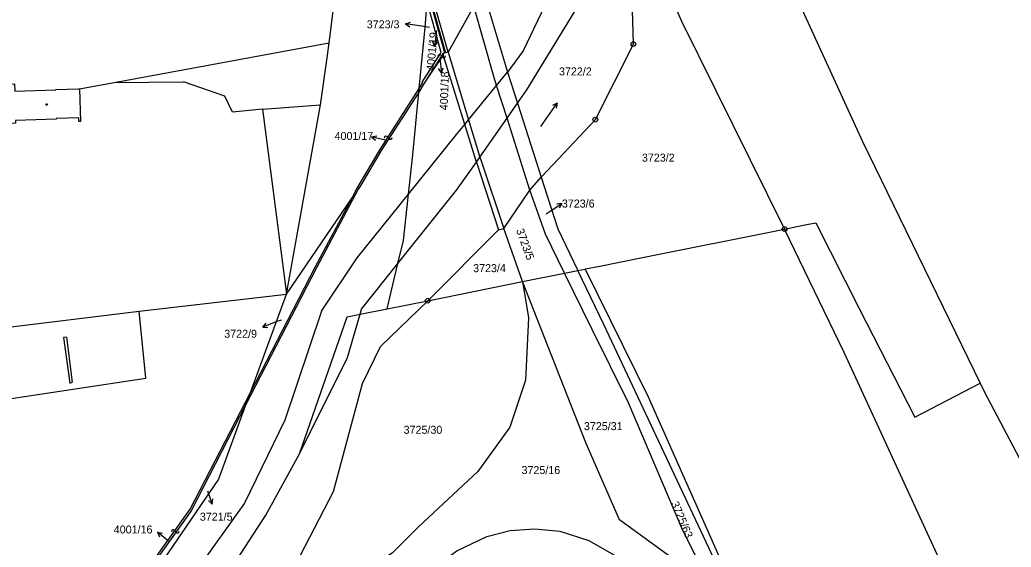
# Model space of a CAD drawing. Extents: x -747779 to -747197, y -965543 to -964919.
# Drawn here: x -747601.4 to -747390.8, y -965349.9 to -965237.8 of the extents above; entities that cross this region are included whole.
import ezdxf

# ---------------------------------------------------------------- set-up
doc = ezdxf.new("R2010")
doc.units = 0
for name, color, linetype in [('Hranice parcel', 7, 'Continuous'), ('Parcelní čísla', 7, 'Continuous'), ('Pop  PČ popisy', 7, 'Continuous'), ('Vnitřní kresba', 7, 'Continuous'), ('Značky bodu BP', 7, 'Continuous'), ('Značky budov', 7, 'Continuous'), ('Značky kultur', 7, 'Continuous')]:
    doc.layers.add(name, color=color, linetype=linetype)

msp = doc.modelspace()

# ---------------------------------------------------------------- linework, layer by layer
at = {"layer": 'Hranice parcel'}
for p, q in [((-747514.75, -965231.66), (-747511.04, -965244.8)), ((-747511.04, -965244.8), (-747511.35, -965244.91)), ((-747515.51, -965251.29), (-747516.68, -965253.18)), ((-747516.68, -965253.18), (-747516.6, -965252.37)), ((-747493.09, -965273.99), (-747490.69, -965271.24)), ((-747498.6, -965282.12), (-747493.09, -965273.99)), ((-747544.78, -965296.1), (-747530.86, -965275.61)), ((-747494.62, -965293.42), (-747498.6, -965282.12)), ((-747494.62, -965293.42), (-747485.73, -965291.64)), ((-747485.73, -965291.64), (-747482.89, -965291.07)), ((-747482.89, -965291.07), (-747481.32, -965290.75)), ((-747514.8, -965297.48), (-747494.62, -965293.42)), ((-747552.46, -965316.97), (-747544.78, -965296.1)), ((-747523.38, -965299.2), (-747514.8, -965297.48)), ((-747553.47, -965319.72), (-747552.46, -965316.97))]:
    msp.add_line(p, q, dxfattribs=at)
for points in [[(-747535.74, -965242.71), (-747531.85, -965211.79), (-747531.66, -965185.87), (-747538.81, -965117.67), (-747546.28, -965074.93), (-747546.46, -965062.18)], [(-747468.41, -965145.2), (-747466.29, -965153.89), (-747464.12, -965160.1), (-747445.94, -965212.26), (-747440.57, -965223.99), (-747422.43, -965263.63), (-747397.43, -965314.99)], [(-747490.69, -965271.24), (-747489.44, -965269.91), (-747487.1, -965267.42), (-747479.18, -965259.01), (-747471.1, -965242.94), (-747471.94, -965213.78), (-747472.02, -965212.77)], [(-747472.02, -965212.77), (-747460.89, -965238.09), (-747438.98, -965282.25)], [(-747514.78, -965232.07), (-747511.25, -965244.76), (-747511.35, -965244.91)], [(-747516.6, -965252.37), (-747515.34, -965239.4), (-747514.92, -965233.94)], [(-747516.6, -965252.37), (-747515.81, -965251.13), (-747515.95, -965251.03), (-747511.95, -965244.73), (-747514.92, -965233.94)], [(-747505, -965234.87), (-747510.48, -965244.69), (-747511.04, -965244.8)], [(-747588.73, -965252.47), (-747581.39, -965251.12), (-747535.74, -965242.71)], [(-747544.78, -965296.1), (-747537.6, -965255.87), (-747536.14, -965245.88), (-747535.74, -965242.71)], [(-747511.35, -965244.91), (-747511.54, -965245.21), (-747515.51, -965251.29)], [(-747511.35, -965244.91), (-747511.61, -965245), (-747515.51, -965251.29)], [(-747633.05, -965255.35), (-747633.06, -965254.31), (-747628.09, -965254.26), (-747628.08, -965255.3), (-747610.07, -965255.11), (-747610.11, -965251.53), (-747602.55, -965251.41), (-747602.51, -965252.93), (-747593.78, -965252.7), (-747593.79, -965252.6), (-747588.97, -965252.48), (-747588.73, -965252.47)], [(-747588.73, -965252.47), (-747588.55, -965259.42), (-747588.9, -965259.43), (-747588.92, -965258.62), (-747593.7, -965258.74), (-747593.7, -965258.94), (-747602.35, -965259.16), (-747602.34, -965259.76), (-747610.02, -965259.88), (-747610.02, -965260.13), (-747632.99, -965260.36), (-747638.07, -965260.41), (-747638.11, -965256.51), (-747633.04, -965256.38), (-747633.05, -965255.35)], [(-747516.68, -965253.18), (-747524.65, -965265.56), (-747529.03, -965272.91), (-747529.53, -965273.75), (-747538.42, -965290.51), (-747553.47, -965319.72)], [(-747530.86, -965275.61), (-747529.79, -965273.6), (-747524.88, -965265.35), (-747516.6, -965252.37)], [(-747523.38, -965299.2), (-747521.12, -965289.61), (-747519.96, -965284.68), (-747518.88, -965274.83), (-747517.97, -965266.5), (-747516.68, -965253.18)], [(-747490.69, -965271.24), (-747487.17, -965282.18), (-747482.89, -965291.07)], [(-747485.73, -965291.64), (-747489.75, -965283.38), (-747493.09, -965273.99)], [(-747552.46, -965316.97), (-747538.72, -965290.33), (-747530.86, -965275.61)], [(-747438.98, -965282.25), (-747435, -965281.45), (-747432.31, -965280.91), (-747423.15, -965299.11), (-747411.34, -965322.23), (-747397.43, -965314.99)], [(-747514.8, -965297.48), (-747499.75, -965282.4), (-747498.6, -965282.12)], [(-747481.32, -965290.75), (-747481.25, -965290.74), (-747478.23, -965290.13), (-747469.86, -965288.45), (-747438.98, -965282.25)], [(-747298.39, -965537.69), (-747318.1, -965501.72), (-747320.58, -965502.66), (-747342.67, -965465.16), (-747352.78, -965470.55), (-747357.13, -965461.03), (-747376, -965418.63), (-747377.18, -965415.98), (-747381.59, -965406.09), (-747382.39, -965404.29), (-747386.82, -965394.33), (-747387.63, -965392.51), (-747387.99, -965391.72), (-747426.3, -965308.51), (-747438.98, -965282.25)], [(-747445.23, -965379.92), (-747447.37, -965372.98), (-747460.79, -965345.82), (-747472.15, -965319.18), (-747479.89, -965303.62), (-747485.73, -965291.64)], [(-747481.32, -965290.75), (-747467.96, -965317.93), (-747448.87, -965361), (-747429.89, -965395.74), (-747424.56, -965401.33), (-747426.57, -965402.17)], [(-747494.62, -965293.42), (-747493.4, -965301.1), (-747494, -965314.35), (-747497.38, -965324.36), (-747504.12, -965333.82), (-747516.76, -965345.53), (-747522.34, -965351.17), (-747542.83, -965364.12), (-747548.91, -965365.21)], [(-747437.34, -965403.35), (-747436.67, -965405.18), (-747441.17, -965397.15), (-747449.31, -965379.9), (-747457.39, -965360.59), (-747463.67, -965351.63), (-747474.03, -965344.07), (-747481.12, -965327.83), (-747494.62, -965293.42)], [(-747647.24, -965306.07), (-747608.41, -965303.66), (-747606.63, -965318.79), (-747574.68, -965313.98), (-747576.1, -965299.7), (-747544.78, -965296.1)], [(-747548.91, -965365.21), (-747534.79, -965338.05), (-747528.66, -965315.08), (-747524.84, -965307.23), (-747514.8, -965297.48)], [(-747661.4, -965470.99), (-747649.22, -965460.69), (-747640.13, -965447.94), (-747625.94, -965426.31), (-747622.59, -965421.5), (-747614.88, -965413.02), (-747613.22, -965411.19), (-747601.34, -965398.13), (-747565.97, -965368.89), (-747549.19, -965343.06), (-747542.01, -965330.04), (-747531.93, -965300.92), (-747529.16, -965300.36), (-747523.38, -965299.2)], [(-747397.43, -965314.99), (-747396.55, -965316.79), (-747356.48, -965392.83), (-747313.39, -965471.85)], [(-747621.4, -965397.45), (-747619.73, -965396.64), (-747619.47, -965397.18), (-747618.61, -965398.65), (-747611.16, -965392.29), (-747589.47, -965372.96), (-747577.69, -965359.27), (-747565.25, -965341.77), (-747552.46, -965316.97)], [(-747553.47, -965319.72), (-747565.02, -965342.13), (-747577.45, -965359.48), (-747589.24, -965373.2), (-747610.98, -965392.52), (-747618.69, -965399.11), (-747619.74, -965397.42), (-747621.17, -965398.11)], [(-747553.47, -965319.72), (-747559.26, -965335.45), (-747575.7, -965359.57), (-747619.13, -965404.01)], [(-747534.71, -965373.37), (-747531.66, -965370.7), (-747512.73, -965353.63), (-747508.57, -965350.62), (-747502.21, -965347.61), (-747497.27, -965346.29), (-747492.14, -965345.95), (-747486.69, -965346.48), (-747480.57, -965348.43), (-747475.22, -965351.48), (-747470.46, -965355.7), (-747466.83, -965360.55), (-747464.83, -965364.53), (-747457, -965384.11)]]:
    msp.add_lwpolyline(points, dxfattribs=at)
at = {"layer": 'Pop  PČ popisy'}
for p, q in [((-747519.49, -965238.62), (-747518.43, -965238.28)), ((-747516.53, -965239.09), (-747519.49, -965238.62)), ((-747519.49, -965238.62), (-747518.58, -965239.27)), ((-747514.4, -965239.42), (-747516.53, -965239.09)), ((-747512.97, -965240.48), (-747513.34, -965243.46)), ((-747512.92, -965240.05), (-747512.97, -965240.48)), ((-747513.34, -965243.46), (-747513.71, -965242.4)), ((-747513.34, -965243.46), (-747512.72, -965242.53)), ((-747512.22, -965246.11), (-747511.85, -965249.09)), ((-747511.85, -965249.09), (-747511.48, -965248.03)), ((-747511.85, -965249.09), (-747512.47, -965248.16)), ((-747526.72, -965262.67), (-747525.63, -965262.43)), ((-747523.81, -965263.4), (-747526.72, -965262.67)), ((-747526.72, -965262.67), (-747525.87, -965263.4)), ((-747523.54, -965263.48), (-747523.81, -965263.4)), ((-747488.8, -965278.49), (-747486.28, -965276.86)), ((-747486.28, -965276.86), (-747487.4, -965276.98)), ((-747486.28, -965276.86), (-747486.85, -965277.82)), ((-747489.64, -965279.04), (-747488.8, -965278.49)), ((-747547.03, -965302.01), (-747549.83, -965303.08)), ((-747549.83, -965303.08), (-747549.08, -965302.26)), ((-747545.92, -965301.59), (-747547.03, -965302.01)), ((-747549.83, -965303.08), (-747548.72, -965303.19)), ((-747561.6, -965337.92), (-747560.57, -965340.74)), ((-747560.57, -965340.74), (-747561.39, -965339.97)), ((-747560.57, -965340.74), (-747560.45, -965339.63)), ((-747569.89, -965348.57), (-747572.22, -965346.68)), ((-747572.22, -965346.68), (-747571.13, -965346.92)), ((-747572.22, -965346.68), (-747571.76, -965347.7))]:
    msp.add_line(p, q, dxfattribs=at)
at = {"layer": 'Vnitřní kresba'}
for p, q in [((-747510.48, -965244.69), (-747514.63, -965230.04)), ((-747489.21, -965233.16), (-747494.5, -965244.38)), ((-747493.76, -965252.69), (-747481.94, -965233.25)), ((-747500.75, -965249.85), (-747505, -965234.87)), ((-747502.29, -965234.04), (-747497.81, -965248.91)), ((-747511.54, -965245.21), (-747511.61, -965245)), ((-747506.93, -965260.03), (-747511.54, -965245.21)), ((-747510.48, -965244.69), (-747506.12, -965259.04)), ((-747494.5, -965244.38), (-747497.81, -965248.91)), ((-747500.15, -965251.76), (-747500.75, -965249.85)), ((-747500.15, -965251.76), (-747497.81, -965248.91)), ((-747497.81, -965248.91), (-747495.71, -965255.5)), ((-747581.39, -965251.12), (-747566.65, -965250.98)), ((-747557.92, -965254.05), (-747566.65, -965250.98)), ((-747506.12, -965259.04), (-747500.15, -965251.76)), ((-747497.94, -965258.71), (-747500.15, -965251.76)), ((-747556.24, -965257.4), (-747557.92, -965254.05)), ((-747495.71, -965255.5), (-747493.76, -965252.69)), ((-747549.92, -965256.78), (-747537.6, -965255.87)), ((-747497.94, -965258.71), (-747495.71, -965255.5)), ((-747495.71, -965255.5), (-747490.69, -965271.24)), ((-747549.92, -965256.78), (-747556.24, -965257.4)), ((-747549.92, -965256.78), (-747544.78, -965296.1)), ((-747508.67, -965262.15), (-747506.93, -965260.03)), ((-747506.93, -965260.03), (-747506.12, -965259.04)), ((-747504.43, -965268.04), (-747506.93, -965260.03)), ((-747506.12, -965259.04), (-747503.7, -965266.99)), ((-747503.7, -965266.99), (-747497.94, -965258.71)), ((-747493.09, -965273.99), (-747497.94, -965258.71)), ((-747518.88, -965274.83), (-747508.67, -965262.15)), ((-747504.43, -965268.04), (-747503.7, -965266.99)), ((-747503.7, -965266.99), (-747503.47, -965267.75)), ((-747508.69, -965274.02), (-747504.43, -965268.04)), ((-747504.43, -965268.04), (-747499.75, -965282.4)), ((-747503.47, -965267.75), (-747498.6, -965282.12)), ((-747529.8, -965288.38), (-747518.88, -965274.83)), ((-747521.12, -965289.61), (-747508.69, -965274.02)), ((-747537.38, -965299.71), (-747529.8, -965288.38)), ((-747528.85, -965299.3), (-747521.12, -965289.61)), ((-747477.38, -965302.52), (-747482.89, -965291.07)), ((-747608.41, -965303.66), (-747576.1, -965299.7)), ((-747537.38, -965299.71), (-747545.12, -965322.86)), ((-747531.84, -965309.54), (-747529.16, -965300.36)), ((-747529.16, -965300.36), (-747528.85, -965299.3)), ((-747444.82, -965371.76), (-747477.38, -965302.52)), ((-747591.52, -965305.21), (-747592.16, -965305.29)), ((-747592.16, -965305.29), (-747590.84, -965315)), ((-747591.52, -965305.21), (-747590.33, -965314.79)), ((-747542.01, -965330.04), (-747531.84, -965309.54)), ((-747590.84, -965315), (-747590.33, -965314.79)), ((-747545.12, -965322.86), (-747553.74, -965340.54)), ((-747553.74, -965340.54), (-747569.56, -965362.6))]:
    msp.add_line(p, q, dxfattribs=at)
at = {"layer": 'Značky bodu BP'}
for centre, radius in [((-747471.1, -965242.94), 0.5), ((-747471.1, -965242.94), 0.0303), ((-747479.18, -965259.01), 0.5), ((-747479.18, -965259.01), 0.0303), ((-747438.98, -965282.25), 0.5), ((-747438.98, -965282.25), 0.0303), ((-747514.8, -965297.48), 0.5), ((-747514.8, -965297.48), 0.0303)]:
    msp.add_circle(centre, radius, dxfattribs=at)
at = {"layer": 'Značky budov'}
for p, q in [((-747511.93, -965245.41), (-747511.73, -965245.67)), ((-747523.29, -965262.74), (-747523.09, -965263)), ((-747568.51, -965346.38), (-747568.31, -965346.64))]:
    msp.add_line(p, q, dxfattribs=at)
msp.add_circle((-747595.74, -965255.79), 0.175, dxfattribs=at)
for centre, start, end in [((-747512.27, -965245.6), 29.2914, 181.2189), ((-747511.39, -965245.48), 209.2914, 1.2189), ((-747523.63, -965262.93), 29.2914, 181.2189), ((-747522.75, -965262.81), 209.2914, 1.2189), ((-747568.85, -965346.57), 29.2914, 181.2189), ((-747567.97, -965346.45), 209.2914, 1.2189)]:
    msp.add_arc(centre, 0.394, start, end, dxfattribs=at)
at = {"layer": 'Značky kultur'}
for p, q in [((-747490.76, -965260.43), (-747487.32, -965255.51)), ((-747487.32, -965255.51), (-747488.29, -965256.03)), ((-747487.32, -965255.51), (-747487.47, -965256.6))]:
    msp.add_line(p, q, dxfattribs=at)

# ---------------------------------------------------------------- texts
at = {"layer": 'Parcelní čísla'}
for s, p in [('3723/3', (-747527.74, -965239.6)), ('3722/2', (-747486.9, -965249.61)), ('4001/17', (-747534.58, -965263.32)), ('3723/2', (-747469.29, -965267.93)), ('3723/6', (-747486.29, -965277.69)), ('3723/4', (-747505.14, -965291.42)), ('3722/9', (-747558.01, -965305.36)), ('3725/31', (-747481.61, -965325)), ('3725/30', (-747519.91, -965325.77)), ('3725/16', (-747494.86, -965334.33)), ('3721/5', (-747563.2, -965344.24)), ('4001/16', (-747581.48, -965346.96))]:
    msp.add_text(s, height=1.7, dxfattribs=at).set_placement(p)
for s, rotation, p in [('4001/19', 85, (-747513.39, -965248.7)), ('4001/18', 88, (-747510.56, -965257.03)), ('3723/5', 290, (-747496.06, -965282.49)), ('3725/63', 293, (-747463.15, -965340.57))]:
    msp.add_text(s, height=1.7, rotation=rotation, dxfattribs=at).set_placement(p)

doc.saveas('drawing.dxf')
